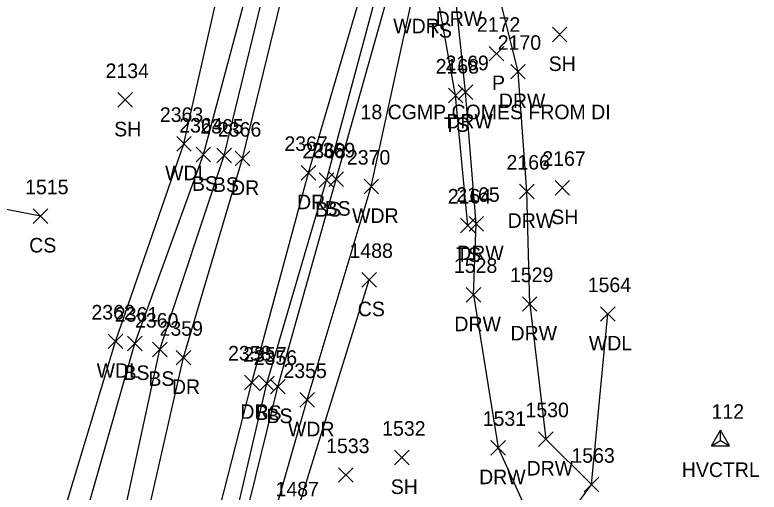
# Model space of a CAD drawing. Extents: x 1761340 to 1763889, y 696770 to 706023.
# Drawn here: x 1761653.6 to 1761755.8, y 700918.1 to 700983.6 of the extents above; entities that cross this region are included whole.
import ezdxf

# ---------------------------------------------------------------- set-up
doc = ezdxf.new("R2010")
doc.units = 0
for name, color, linetype in [('C_A', 7, 'Continuous'), ('C_I', 7, 'Continuous'), ('CPSM', 7, 'Continuous'), ('D_A', 7, 'Continuous'), ('D_C', 7, 'Continuous'), ('D_I', 7, 'Continuous'), ('D_TIC', 7, 'Continuous'), ('L_A', 7, 'Continuous'), ('L_I', 7, 'Continuous'), ('L_TIC', 7, 'Continuous'), ('LAWA', 7, 'Continuous'), ('LELB', 7, 'Continuous'), ('R_A', 7, 'Continuous'), ('R_I', 7, 'Continuous'), ('R_TIC', 7, 'Continuous'), ('RDP', 7, 'Continuous'), ('RDW', 7, 'Continuous')]:
    doc.layers.add(name, color=color, linetype=linetype)

msp = doc.modelspace()

# ---------------------------------------------------------------- linework, layer by layer
at = {"layer": 'CPSM'}
for p, q in [((1761749.22, 700924.48), (1761750.47, 700926.65)), ((1761751.72, 700924.48), (1761750.47, 700926.65)), ((1761750.47, 700925.21), (1761750.47, 700926.65)), ((1761749.22, 700924.48), (1761750.47, 700925.21)), ((1761750.47, 700925.21), (1761750.47, 700925.21)), ((1761750.47, 700925.21), (1761751.72, 700924.48)), ((1761749.22, 700924.48), (1761751.72, 700924.48))]:
    msp.add_line(p, q, dxfattribs=at)
at = {"layer": 'D_TIC'}
for points in [[(1761718.75, 700977.32), (1761720.75, 700979.32)], [(1761720.75, 700977.32), (1761718.75, 700979.32)]]:
    msp.add_lwpolyline(points, dxfattribs=at)
at = {"layer": 'L_TIC'}
for points in [[(1761727.41, 700979.94), (1761729.41, 700981.94)], [(1761729.41, 700979.94), (1761727.41, 700981.94)], [(1761667.79, 700970.97), (1761669.79, 700972.97)], [(1761669.79, 700970.97), (1761667.79, 700972.97)], [(1761713.13, 700971.59), (1761715.13, 700973.59)], [(1761715.13, 700971.59), (1761713.13, 700973.59)], [(1761675.85, 700964.95), (1761677.85, 700966.95)], [(1761677.85, 700964.95), (1761675.85, 700966.95)], [(1761678.51, 700963.49), (1761680.51, 700965.49)], [(1761680.51, 700963.49), (1761678.51, 700965.49)], [(1761681.38, 700963.35), (1761683.38, 700965.35)], [(1761683.38, 700963.35), (1761681.38, 700965.35)], [(1761695.4, 700959.96), (1761697.4, 700961.96)], [(1761697.4, 700959.96), (1761695.4, 700961.96)], [(1761696.72, 700960.08), (1761698.72, 700962.08)], [(1761698.72, 700960.08), (1761696.72, 700962.08)], [(1761701.56, 700959.09), (1761703.56, 700961.09)], [(1761703.56, 700959.09), (1761701.56, 700961.09)], [(1761727.77, 700958.92), (1761729.77, 700960.92)], [(1761729.77, 700958.92), (1761727.77, 700960.92)], [(1761656.17, 700955.03), (1761658.17, 700957.03)], [(1761658.17, 700955.03), (1761656.17, 700957.03)], [(1761714.79, 700953.75), (1761716.79, 700955.75)], [(1761716.79, 700953.75), (1761714.79, 700955.75)], [(1761701.26, 700946.28), (1761703.26, 700948.28)], [(1761703.26, 700946.28), (1761701.26, 700948.28)], [(1761734, 700941.59), (1761736, 700943.59)], [(1761736, 700941.59), (1761734, 700943.59)], [(1761666.45, 700937.83), (1761668.45, 700939.83)], [(1761668.45, 700937.83), (1761666.45, 700939.83)], [(1761669.1, 700937.53), (1761671.1, 700939.53)], [(1761671.1, 700937.53), (1761669.1, 700939.53)], [(1761672.53, 700936.72), (1761674.53, 700938.72)], [(1761674.53, 700936.72), (1761672.53, 700938.72)], [(1761687.23, 700932.04), (1761689.23, 700934.04)], [(1761689.23, 700932.04), (1761687.23, 700934.04)], [(1761688.74, 700931.61), (1761690.74, 700933.61)], [(1761690.74, 700931.61), (1761688.74, 700933.61)], [(1761692.76, 700929.8), (1761694.76, 700931.8)], [(1761694.76, 700929.8), (1761692.76, 700931.8)], [(1761705.74, 700921.88), (1761707.74, 700923.88)], [(1761707.74, 700921.88), (1761705.74, 700923.88)], [(1761698.06, 700919.49), (1761700.06, 700921.49)], [(1761700.06, 700919.49), (1761698.06, 700921.49)], [(1761731.76, 700918.17), (1761733.76, 700920.17)], [(1761733.76, 700918.17), (1761731.76, 700920.17)]]:
    msp.add_lwpolyline(points, dxfattribs=at)
at = {"layer": 'LAWA'}
for points in [[(1761667.45, 700938.83), (1761676.85, 700965.95), (1761685.84, 701005.78), (1761682.94, 701010.81), (1761682.17, 701016.5), (1761683.01, 701019.11), (1761683.74, 701022.58), (1761694.2, 701030.75), (1761696.86, 701041.57), (1761703.63, 701062.52), (1761706.63, 701075.37), (1761702.24, 701098.48), (1761699.3, 701099.16), (1761706.74, 701121.1), (1761714.05, 701139.55)], [(1761683.19, 700893.77), (1761693.76, 700930.8), (1761702.56, 700960.09), (1761708.21, 700986.11), (1761709.81, 700994.41), (1761714.45, 701002.91), (1761720.39, 701013.78), (1761724.65, 701022.11), (1761723.36, 701026.16), (1761723.24, 701034.18), (1761732.59, 701076.41), (1761747, 701128.03)], [(1761696.4, 700877.13), (1761722.27, 700862.97), (1761723.72, 700872.01), (1761721.64, 700895.63), (1761726.28, 700910.33), (1761732.76, 700919.17), (1761735, 700942.59)], [(1761656.53, 700902.64), (1761667.45, 700938.83)]]:
    msp.add_lwpolyline(points, dxfattribs=at)
at = {"layer": 'LELB'}
for points in [[(1761681.3, 700585.52), (1761671.93, 700613.51), (1761667.59, 700648.27), (1761662.96, 700684.4), (1761660.97, 700720.86), (1761660.49, 700762.08), (1761662.81, 700791.59), (1761666.16, 700822.15), (1761669.09, 700835.75), (1761669.55, 700847.22), (1761671.38, 700859.7), (1761679.65, 700896.38), (1761688.23, 700933.04), (1761696.4, 700960.96), (1761706.35, 700997.91), (1761723.36, 701026.16)], [(1761684.45, 700586.47), (1761674.15, 700613.84), (1761669.56, 700648.24), (1761665.94, 700684.58), (1761663.69, 700720.73), (1761662.67, 700762.27), (1761665.11, 700791.25), (1761666.95, 700822.18), (1761669.97, 700835.61), (1761670.38, 700847.09), (1761671.95, 700859.51), (1761680.67, 700895.81), (1761689.74, 700932.61), (1761697.72, 700961.08), (1761707.94, 700997.33), (1761724.65, 701022.11)], [(1761650.67, 700568.58), (1761653.72, 700589.35), (1761656.23, 700611.85), (1761650.78, 700645.88), (1761646.69, 700682.27), (1761643.97, 700721.14), (1761646.18, 700763.15), (1761649, 700791.97), (1761651.08, 700826.68), (1761655.56, 700862.86), (1761665.44, 700900.35), (1761673.53, 700937.72), (1761682.38, 700964.35), (1761693, 701008.08), (1761690.13, 701015.34), (1761683.01, 701019.11)], [(1761647.36, 700568.69), (1761651.51, 700589.64), (1761652.18, 700611.17), (1761648.15, 700645.92), (1761644.28, 700683.03), (1761641.56, 700721.37), (1761643.75, 700763.66), (1761644.59, 700792.45), (1761648.47, 700827.4), (1761652.74, 700863.51), (1761659.58, 700901.67), (1761670.1, 700938.53), (1761679.51, 700964.49), (1761691.19, 701008.19), (1761682.17, 701016.5)], [(1761715.79, 700954.75), (1761714.13, 700972.59), (1761711.79, 700985.52)], [(1761657.17, 700956.03), (1761642.83, 700958.81), (1761635.36, 700949.87), (1761640.79, 700937.2), (1761637.34, 700929.97), (1761628.72, 700941.73), (1761634.08, 700962.31)], [(1761685.44, 700885), (1761692.11, 700914.55), (1761702.26, 700947.28)]]:
    msp.add_lwpolyline(points, dxfattribs=at)
at = {"layer": 'R_TIC'}
for points in [[(1761721.69, 700974.85), (1761723.69, 700976.85)], [(1761723.69, 700974.85), (1761721.69, 700976.85)], [(1761714.48, 700972.05), (1761716.48, 700974.05)], [(1761716.48, 700972.05), (1761714.48, 700974.05)], [(1761683.87, 700962.93), (1761685.87, 700964.93)], [(1761685.87, 700962.93), (1761683.87, 700964.93)], [(1761692.93, 700960.97), (1761694.93, 700962.97)], [(1761694.93, 700960.97), (1761692.93, 700962.97)], [(1761722.9, 700958.41), (1761724.9, 700960.41)], [(1761724.9, 700958.41), (1761722.9, 700960.41)], [(1761715.97, 700953.98), (1761717.97, 700955.98)], [(1761717.97, 700953.98), (1761715.97, 700955.98)], [(1761715.59, 700944.23), (1761717.59, 700946.23)], [(1761717.59, 700944.23), (1761715.59, 700946.23)], [(1761723.29, 700942.96), (1761725.29, 700944.96)], [(1761725.29, 700942.96), (1761723.29, 700944.96)], [(1761675.77, 700935.6), (1761677.77, 700937.6)], [(1761677.77, 700935.6), (1761675.77, 700937.6)], [(1761685.16, 700932.2), (1761687.16, 700934.2)], [(1761687.16, 700932.2), (1761685.16, 700934.2)], [(1761725.5, 700924.42), (1761727.5, 700926.42)], [(1761727.5, 700924.42), (1761725.5, 700926.42)], [(1761718.98, 700923.23), (1761720.98, 700925.23)], [(1761720.98, 700923.23), (1761718.98, 700925.23)], [(1761731.76, 700918.17), (1761733.76, 700920.17)], [(1761733.76, 700918.17), (1761731.76, 700920.17)]]:
    msp.add_lwpolyline(points, dxfattribs=at)
at = {"layer": 'RDP'}
for points in [[(1761671.26, 700538.43), (1761661.64, 700574.62), (1761657.61, 700611.79), (1761653.18, 700645.74), (1761649.93, 700682.03), (1761646.9, 700721.23), (1761649.1, 700763.06), (1761651.35, 700791.61), (1761653.66, 700826.22), (1761659.48, 700861.88), (1761668.31, 700899.37), (1761676.77, 700936.6), (1761684.87, 700963.93), (1761695.51, 701007.43), (1761695.75, 701009.14), (1761702.96, 701038.72), (1761714.69, 701083.39), (1761730.25, 701133.73)], [(1761685.9, 700541.84), (1761678.4, 700578.09), (1761669.59, 700613.17), (1761665.81, 700647.63), (1761660.31, 700684.32), (1761659.55, 700721.03), (1761658.73, 700762.09), (1761660.8, 700791.69), (1761663.62, 700822.45), (1761666.15, 700836.34), (1761667.52, 700847.08), (1761668.95, 700859.68), (1761676.88, 700896.8), (1761686.16, 700933.2), (1761693.93, 700961.97), (1761704.59, 700998.32), (1761705.06, 700999.04), (1761715.84, 701034.88), (1761727.08, 701077.74), (1761742.29, 701129.68)]]:
    msp.add_lwpolyline(points, dxfattribs=at)
at = {"layer": 'RDW'}
for points in [[(1761723.9, 700959.41), (1761722.69, 700975.85), (1761719.38, 700989.29)], [(1761716.97, 700954.98), (1761715.48, 700973.05), (1761714.02, 700987.14)], [(1761724.29, 700943.96), (1761723.9, 700959.41)], [(1761716.59, 700945.23), (1761716.97, 700954.98)], [(1761716.59, 700945.23), (1761719.98, 700924.23), (1761726.28, 700910.33)], [(1761724.29, 700943.96), (1761726.5, 700925.42), (1761732.76, 700919.17)]]:
    msp.add_lwpolyline(points, dxfattribs=at)

# ---------------------------------------------------------------- texts
at = {"layer": 'C_A'}
msp.add_text('HVCTRL', height=2, dxfattribs=at).set_placement((1761745.17, 700920.21))
at = {"layer": 'C_I'}
msp.add_text('112', height=2, dxfattribs=at).set_placement((1761749.25, 700928.21))
at = {"layer": 'D_A'}
msp.add_text('P', height=2, dxfattribs=at).set_placement((1761719.12, 700973.32))
at = {"layer": 'D_C'}
msp.add_text('18 CGMP COMES FROM DI', height=2, dxfattribs=at).set_placement((1761701.08, 700969.32))
at = {"layer": 'D_I'}
msp.add_text('2172', height=2, dxfattribs=at).set_placement((1761717.05, 700981.32))
at = {"layer": 'L_A'}
for s, p in [('WDR', (1761705.57, 700981.11)), ('TS', (1761710.2, 700980.52)), ('SH', (1761726.9, 700975.94)), ('SH', (1761667.27, 700966.97)), ('TS', (1761712.54, 700967.59)), ('WDL', (1761674.26, 700960.95)), ('BS', (1761677.95, 700959.49)), ('BS', (1761680.82, 700959.35)), ('BS', (1761694.84, 700955.96)), ('BS', (1761696.16, 700956.08)), ('WDR', (1761699.92, 700955.09)), ('SH', (1761727.26, 700954.92)), ('CS', (1761655.61, 700951.03)), ('TS', (1761714.2, 700949.75)), ('CS', (1761700.7, 700942.28)), ('WDL', (1761732.41, 700937.59)), ('WDL', (1761664.87, 700933.83)), ('BS', (1761668.55, 700933.53)), ('BS', (1761671.97, 700932.72)), ('BS', (1761686.67, 700928.04)), ('BS', (1761688.18, 700927.61)), ('WDR', (1761691.12, 700925.8)), ('SH', (1761705.23, 700917.88))]:
    msp.add_text(s, height=2, dxfattribs=at).set_placement(p)
at = {"layer": 'L_I'}
for s, p in [('2134', (1761666.09, 700974.97)), ('2168', (1761711.39, 700975.59)), ('2363', (1761673.54, 700968.95)), ('2364', (1761676.2, 700967.49)), ('2365', (1761679.08, 700967.35)), ('2368', (1761693.1, 700963.96)), ('2369', (1761694.4, 700964.08)), ('2370', (1761699.21, 700963.09)), ('2167', (1761726.03, 700962.92)), ('1515', (1761655.05, 700959.03)), ('2164', (1761713.05, 700957.75)), ('1488', (1761699.57, 700950.28)), ('1564', (1761732.26, 700945.59)), ('2362', (1761664.15, 700941.83)), ('2361', (1761667.36, 700941.53)), ('2360', (1761670.13, 700940.72)), ('2357', (1761684.97, 700936.04)), ('2356', (1761686.42, 700935.61)), ('2355', (1761690.5, 700933.8)), ('1532', (1761704.05, 700925.88)), ('1533', (1761696.36, 700923.49)), ('1563', (1761730.02, 700922.17)), ('1487', (1761689.42, 700917.55))]:
    msp.add_text(s, height=2, dxfattribs=at).set_placement(p)
at = {"layer": 'R_A'}
for s, p in [('DRW', (1761711.39, 700982.14)), ('DRW', (1761720.06, 700970.85)), ('DRW', (1761712.85, 700968.05)), ('DR', (1761683.31, 700958.93)), ('DR', (1761692.37, 700956.97)), ('DRW', (1761721.27, 700954.41)), ('DRW', (1761714.34, 700949.98)), ('DRW', (1761713.96, 700940.23)), ('DRW', (1761721.66, 700938.96)), ('DR', (1761675.2, 700931.6)), ('DR', (1761684.59, 700928.2)), ('DRW', (1761723.87, 700920.42)), ('DRW', (1761717.35, 700919.23))]:
    msp.add_text(s, height=2, dxfattribs=at).set_placement(p)
at = {"layer": 'R_I'}
for s, p in [('2170', (1761719.91, 700978.85)), ('2169', (1761712.73, 700976.05)), ('2366', (1761681.51, 700966.93)), ('2367', (1761690.63, 700964.97)), ('2166', (1761721.11, 700962.41)), ('2165', (1761714.23, 700957.98)), ('1528', (1761713.9, 700948.23)), ('1529', (1761721.59, 700946.96)), ('2359', (1761673.5, 700939.6)), ('2358', (1761682.9, 700936.2)), ('1530', (1761723.72, 700928.42)), ('1531', (1761717.85, 700927.23)), ('1563', (1761730.02, 700922.17))]:
    msp.add_text(s, height=2, dxfattribs=at).set_placement(p)

doc.saveas('drawing.dxf')
